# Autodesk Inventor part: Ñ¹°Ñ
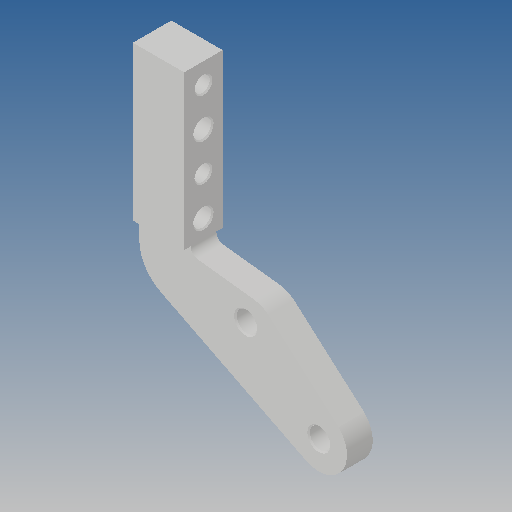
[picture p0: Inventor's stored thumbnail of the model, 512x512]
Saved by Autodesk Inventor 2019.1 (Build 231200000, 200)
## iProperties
Created: 2012-10
Part Number: Ñ¹°Ñ
Material: Ogólny
Document SubType Name: Modeling
Designer: CADENGINEERING4
Density: 1 g/cm^3
Appearance: Domyślna
Author: CADENGINEERING4
Revision Number: ÈÎºÎ
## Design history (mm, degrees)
feature "µ¹½Ç2"
node "Bryła1"
